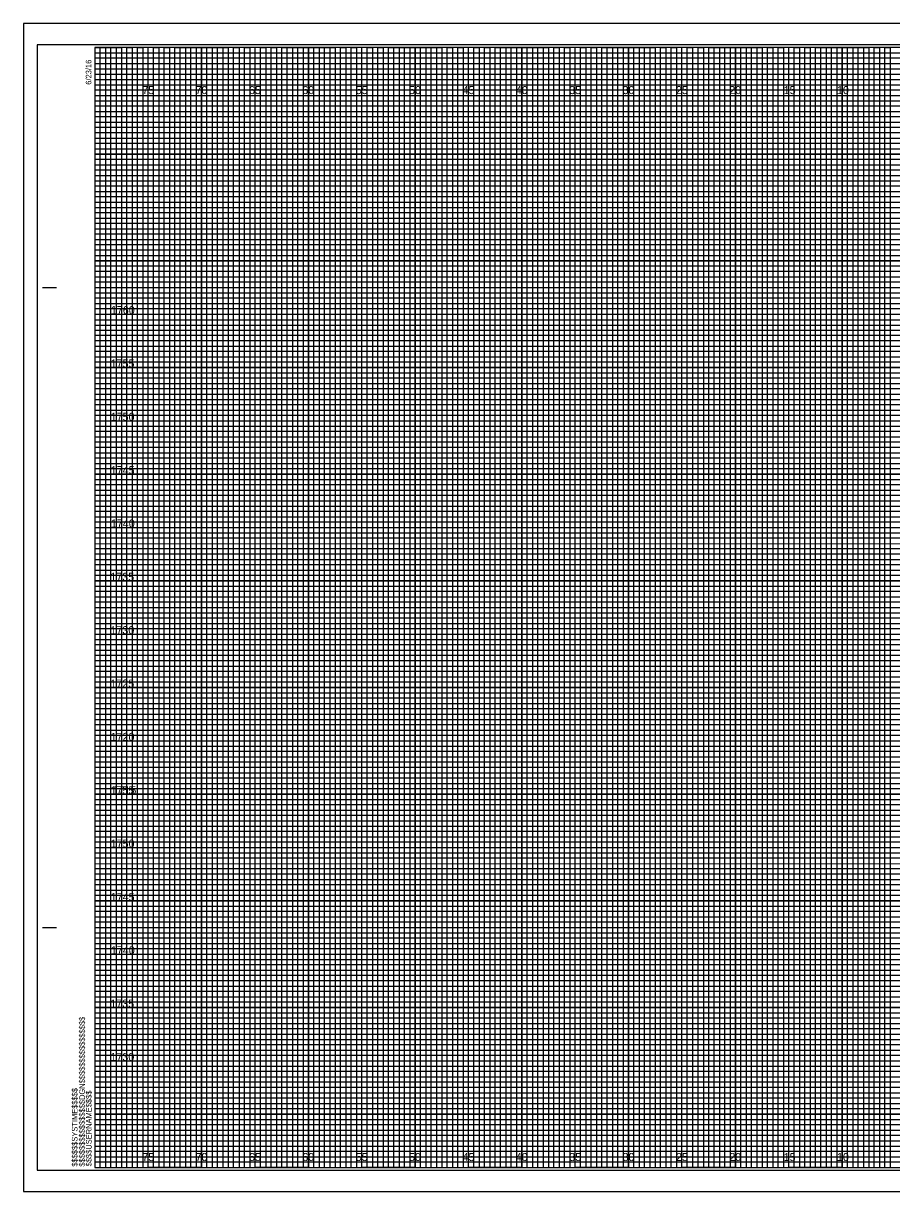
# Model space of a CAD drawing. Extents: x -7 to 162, y -2 to 437.
# Drawn here: x -6.7 to 74.6, y -2.3 to 107.3 of the extents above; entities that cross this region are included whole.
import ezdxf

# ---------------------------------------------------------------- set-up
doc = ezdxf.new("R2010")
doc.units = 0
for name, color, linetype in [('Raster_Level_0', 7, 'Continuous'), ('Scratch_Level_3', 7, 'Continuous'), ('Sheet Cross Section CELL', 7, 'Continuous'), ('Sheet Cross Section Grid Major CELL', 7, 'Continuous'), ('Sheet Cross Section Grid Middle CELL', 7, 'Continuous'), ('Sheet Cross Section Grid Minor 1 CELL', 7, 'Continuous'), ('Sheet Cross Section Grid Minor 2 CELL', 7, 'Continuous'), ('Sheet Cutting Line CELL', 7, 'Continuous'), ('Sheet DOT Grid CELL', 7, 'Continuous'), ('Sheet Plot Border Inside CELL', 7, 'Continuous'), ('Sheet Plot Border Outside CELL', 7, 'Continuous')]:
    doc.layers.add(name, color=color, linetype=linetype)

msp = doc.modelspace()

# ---------------------------------------------------------------- linework, layer by layer
at = {"layer": 'Sheet Cross Section CELL'}
for p, q in [((-4.9, 82.5), (-3.65, 82.5)), ((-4.85, 82.5), (-3.6, 82.5)), ((-4.9, 22.5), (-3.65, 22.5)), ((-4.85, 22.5), (-3.6, 22.5)), ((0, 0), (0, 0)), ((0, 0), (0, 0)), ((0, 0), (0, 0)), ((0, 0), (0, 0)), ((0, 0), (0, 0)), ((0, 0), (0, 0)), ((0, 0), (0, 0))]:
    msp.add_line(p, q, dxfattribs=at)
msp.add_lwpolyline([(160, 105), (0, 105), (0, 0), (160, 0)], close=True, dxfattribs=at)
at = {"layer": 'Sheet Cross Section Grid Major CELL'}
for p, q in [((5, 105), (0, 105)), ((5, 0), (5, 105)), ((15, 105), (10, 105)), ((10, 105), (10, 0)), ((15, 0), (15, 105)), ((25, 105), (20, 105)), ((20, 105), (20, 0)), ((25, 0), (25, 105)), ((35, 105), (30, 105)), ((30, 105), (30, 0)), ((35, 0), (35, 105)), ((45, 105), (40, 105)), ((40, 105), (40, 0)), ((45, 0), (45, 105)), ((55, 105), (50, 105)), ((50, 105), (50, 0)), ((55, 0), (55, 105)), ((65, 105), (60, 105)), ((60, 105), (60, 0)), ((65, 0), (65, 105)), ((75, 105), (70, 105)), ((70, 105), (70, 0)), ((10, 0), (5, 0)), ((20, 0), (15, 0)), ((30, 0), (25, 0)), ((40, 0), (35, 0)), ((50, 0), (45, 0)), ((60, 0), (55, 0)), ((70, 0), (65, 0))]:
    msp.add_line(p, q, dxfattribs=at)
for points in [[(0, 100), (160, 100), (160, 95), (0, 95)], [(0, 90), (160, 90), (160, 85), (0, 85)], [(0, 80), (160, 80), (160, 75), (0, 75)], [(0, 70), (160, 70), (160, 65), (0, 65)], [(0, 60), (160, 60), (160, 55), (0, 55)], [(0, 50), (160, 50), (160, 45), (0, 45)], [(0, 40), (160, 40), (160, 35), (0, 35)], [(0, 30), (160, 30), (160, 25), (0, 25)], [(0, 20), (160, 20), (160, 15), (0, 15)], [(0, 10), (160, 10), (160, 5), (0, 5)]]:
    msp.add_lwpolyline(points, dxfattribs=at)
at = {"layer": 'Sheet Cross Section Grid Middle CELL'}
for points in [[(0, 105), (2.5, 105), (2.5, 0), (7.5, 0), (7.5, 105), (12.5, 105), (12.5, 0), (17.5, 0), (17.5, 105), (22.5, 105), (22.5, 0), (27.5, 0), (27.5, 105), (32.5, 105), (32.5, 0), (37.5, 0), (37.5, 105), (42.5, 105), (42.5, 0), (47.5, 0), (47.5, 105), (52.5, 105), (52.5, 0), (57.5, 0), (57.5, 105), (62.5, 105), (62.5, 0), (67.5, 0), (67.5, 105), (72.5, 105), (72.5, 0), (77.5, 0)], [(0, 102.5), (137.5, 102.5)], [(0, 92.5), (160, 92.5), (160, 97.5), (0, 97.5)], [(0, 82.5), (160, 82.5), (160, 87.5), (0, 87.5)], [(0, 72.5), (160, 72.5), (160, 77.5), (0, 77.5)], [(0, 62.5), (160, 62.5), (160, 67.5), (0, 67.5)], [(0, 52.5), (160, 52.5), (160, 57.5), (0, 57.5)], [(0, 42.5), (160, 42.5), (160, 47.5), (0, 47.5)], [(0, 32.5), (160, 32.5), (160, 37.5), (0, 37.5)], [(0, 22.5), (160, 22.5), (160, 27.5), (0, 27.5)], [(0, 12.5), (160, 12.5), (160, 17.5), (0, 17.5)], [(0, 2.5), (160, 2.5), (160, 7.5), (0, 7.5)]]:
    msp.add_lwpolyline(points, dxfattribs=at)
at = {"layer": 'Sheet Cross Section Grid Minor 1 CELL'}
for p, q in [((0, 104.5), (130, 104.5)), ((130, 103.99), (0, 103.99)), ((0, 103.99), (0, 103.5)), ((0, 103.5), (130, 103.5)), ((130, 102.95), (0, 102.95)), ((0, 102.95), (0, 102)), ((0, 102), (160, 102))]:
    msp.add_line(p, q, dxfattribs=at)
for points in [[(0, 101.5), (135, 101.5), (160, 101.5), (160, 101), (0, 101)], [(0, 100.5), (160, 100.5), (160, 99.5), (0, 99.5)], [(0, 99), (160, 99), (160, 98.5), (0, 98.49)], [(0, 98), (160, 98), (160, 97), (0, 97)], [(0, 96.5), (160, 96.5), (160, 96), (0, 96)], [(0, 95.5), (160, 95.5), (160, 94.5), (0, 94.5)], [(0, 94), (160, 94), (160, 93.5), (0, 93.5)], [(0, 93), (160, 93), (160, 92), (0, 92)], [(0, 91.5), (160, 91.5), (160, 91), (0, 91)], [(0, 90.5), (160, 90.5), (160, 89.5), (0, 89.5)], [(0, 89), (160, 89), (160, 88.5), (0, 88.5)], [(0, 88), (160, 88), (160, 86.98), (160, 86.5), (160, 86), (0, 86)], [(0, 87), (160, 87), (160, 86.5), (0, 86.5)], [(0, 85.5), (160, 85.5), (160, 84.5), (0, 84.52)], [(0, 84.52), (160, 84.5), (160, 84), (0, 84)], [(0, 83.5), (160, 83.5), (160, 83), (0, 83)], [(0, 82), (160, 82), (160, 81.5), (0, 81.5)], [(0, 81), (160, 81), (160, 80.5), (0, 80.5)], [(-0.04, 79.45), (160, 79.45), (160, 78.94), (-0.04, 78.94)], [(0, 78.5), (160, 78.5), (160, 78), (0, 78)], [(0, 77), (160, 77), (160, 76.5), (0, 76.5)], [(0, 76), (160, 76), (160, 75.5), (0, 75.5)], [(0, 74.5), (160, 74.5), (160, 74), (0, 74)], [(0, 73.5), (160, 73.5), (160, 73), (0, 73)], [(0, 72), (160, 72), (160, 71.5), (0, 71.5)], [(0, 71), (160, 71), (160, 70.5), (0, 70.5)], [(0, 69.5), (160, 69.5), (160, 68.99), (0, 69)], [(0, 68.5), (160, 68.5), (160, 68), (0, 68)], [(0, 67), (160, 67), (160, 66.5), (0, 66.5)], [(0, 66), (160, 66), (160, 65.5), (0, 65.5)], [(0, 64.5), (160, 64.5), (160, 64), (0, 64)], [(0, 63.5), (160, 63.5), (160, 63), (0, 63)], [(0, 62), (160, 62), (160, 61.5), (0, 61.5)], [(0, 61), (160, 61), (160, 60.5), (0, 60.5)], [(0, 59.5), (160, 59.5), (160, 59), (0, 59)], [(0, 58.5), (160.03, 58.45), (160, 58), (0, 58)], [(0, 57), (160, 57), (160, 56.5), (0, 56.5)], [(0, 56), (160, 56), (160, 55.5), (0, 55.5)], [(0, 54.5), (160, 54.5), (160, 54), (0, 54)], [(0, 53.5), (160, 53.5), (160, 53), (0, 53)], [(0, 52), (160, 52), (160, 51.5), (0, 51.5)], [(0, 51), (160, 51), (160, 50.5), (0, 50.5)], [(0, 49.5), (160, 49.5), (160, 49), (0, 49)], [(0, 48.5), (160, 48.5), (160, 48), (0, 48)], [(0, 47), (160, 47), (160, 46.5), (0, 46.5)], [(0, 46), (160, 46), (160, 45.5), (0, 45.5)], [(0, 44.5), (160, 44.5), (160, 44), (0, 44)], [(0, 43.5), (160, 43.5), (160, 43), (0, 43)], [(0, 42), (160, 42), (160, 41.5), (0, 41.5)], [(0, 41), (160, 41), (160, 40.5), (0, 40.5)], [(0, 39.5), (160, 39.5), (160, 38.99), (0, 39)], [(0, 38.5), (160, 38.5), (160, 38), (0, 38)], [(0, 37), (160, 37), (160, 36.5), (0, 36.5)], [(0, 36), (160, 36), (160, 35.5), (0, 35.5)], [(0, 34.5), (160, 34.5), (160, 34), (0, 34)], [(0, 33.5), (160, 33.5), (160, 33), (0, 33)], [(0, 32), (160, 32), (160, 31.5), (0, 31.5)], [(0, 31), (160, 31), (160, 30.5), (0, 30.5)], [(0, 29.5), (160, 29.5), (160, 29), (0, 29)], [(0, 28.5), (160.03, 28.46), (160, 28), (0, 28)], [(0, 27), (160, 27), (160, 26.5), (0, 26.5)], [(0, 26), (160, 26), (160, 25.5), (0, 25.5)], [(0, 24.5), (160, 24.5), (160, 24), (0, 24)], [(0, 23.5), (160, 23.5), (160, 23), (0, 23)], [(0, 22), (160, 22), (160, 21.5), (0, 21.5)], [(0, 21), (160, 21), (160, 20.5), (0, 20.5)], [(0, 19.5), (160, 19.5), (160, 19), (0, 19)], [(0, 18.5), (160, 18.5), (160, 18), (0, 18)], [(0, 17), (160, 17), (160, 16.5), (0, 16.5)], [(0, 16), (160, 16), (160, 15.5), (0, 15.5)], [(0, 14.5), (160, 14.5), (160, 14), (0, 14)], [(0, 13.5), (160, 13.5), (160, 13), (0, 13)], [(0, 12), (160, 12), (160, 11.5), (0, 11.5)], [(0, 11), (160, 11), (160, 10.5), (0, 10.5)], [(0, 9.5), (160, 9.5), (160, 9), (0, 9)], [(0, 8.5), (160, 8.5), (160, 8), (0, 8)], [(0, 7), (160, 7), (160, 6.5), (0, 6.5)], [(0, 6), (160, 6), (160, 5.5), (0, 5.5)], [(0, 4.5), (160, 4.5), (160, 4), (0, 4)], [(0, 3.5), (160, 3.5), (160, 3), (0, 3)], [(0, 2), (160, 2), (160, 1.5), (0, 1.5)], [(0, 1), (160, 1), (160, 0.5), (0, 0.5)]]:
    msp.add_lwpolyline(points, dxfattribs=at)
at = {"layer": 'Sheet Cross Section Grid Minor 2 CELL'}
for points in [[(0, 0), (0.5, 0), (0.5, 105), (1, 105), (1, 0)], [(1, 0), (1.5, 0), (1.5, 105), (2, 105), (2, 0)], [(2.5, 0), (3, 0), (3, 105), (3.5, 105), (3.5, 0)], [(3.5, 0), (4, 0), (4, 105), (4.5, 105), (4.5, 0)], [(5, 0), (5.5, 0), (5.5, 105), (6, 105), (6, 0)], [(6, 0), (6.5, 0), (6.5, 105), (7, 105), (7, 0)], [(7.5, 0), (8, 0), (8, 105), (8.5, 105), (8.5, 0)], [(8.5, 0), (9, 0), (9, 105), (9.5, 105), (9.5, 0)], [(10, 0), (10.5, 0), (10.5, 105), (11, 105), (11, 0)], [(11, 0), (11.5, 0), (11.5, 105), (12, 105), (12, 0)], [(12.5, 0), (13, 0), (13, 105), (13.5, 105), (13.5, 0)], [(13.5, 0), (14, 0), (14, 105), (14.5, 105), (14.5, 0)], [(15, 0), (15.5, 0), (15.5, 105), (16, 105), (16, 0)], [(16, 0), (16.5, 0), (16.5, 105), (17, 105), (17, 0)], [(17.5, 0), (18, 0), (18, 105), (18.5, 105), (18.5, 0)], [(18.5, 0), (19, 0), (19, 105), (19.5, 105), (19.5, 0)], [(20, 0), (20.5, 0), (20.5, 105), (21, 105), (21, 0)], [(21, 0), (21.5, 0), (21.5, 105), (22, 105), (22, 0)], [(22.5, 0), (23, 0), (23, 105), (23.5, 105), (23.5, 0)], [(23.5, 0), (24, 0), (24, 105), (24.5, 105), (24.5, 0)], [(25, 0), (25.5, 0), (25.5, 105), (26, 105), (26, 0)], [(26, 0), (26.5, 0), (26.5, 105), (27, 105), (27, 0)], [(27.5, 0), (28, 0), (28, 105), (28.5, 105), (28.5, 0)], [(28.5, 0), (29, 0), (29, 105), (29.5, 105), (29.5, 0)], [(30, 0), (30.5, 0), (30.5, 105), (31, 105), (31, 0)], [(31, 0), (31.5, 0), (31.5, 105), (32, 105), (32, 0)], [(32.5, 0), (33, 0), (33, 105), (33.5, 105), (33.5, 0)], [(33.5, 0), (34, 0), (34, 105), (34.5, 105), (34.5, 0)], [(35, 0), (35.5, 0), (35.5, 105), (36, 105), (36, 0)], [(36, 0), (36.5, 0), (36.5, 105), (37, 105), (37, 0)], [(37.5, 0), (38, 0), (38, 105), (38.5, 105), (38.5, 0)], [(38.5, 0), (39, 0), (39, 105), (39.5, 105), (39.5, 0)], [(40, 0), (40.5, 0), (40.5, 105), (41, 105), (41, 0)], [(41, 0), (41.5, 0), (41.5, 105), (42, 105), (42, 0)], [(42.5, 0), (43, 0), (43, 105), (43.5, 105), (43.5, 0)], [(43.5, 0), (44, 0), (44, 105), (44.5, 105), (44.5, 0)], [(45, 0), (45.5, 0), (45.5, 105), (46, 105), (46, 0)], [(46, 0), (46.5, 0), (46.5, 105), (47, 105), (47, 0)], [(47.5, 0), (48, 0), (48, 105), (48.5, 105), (48.5, 0)], [(48.5, 0), (49, 0), (49, 105), (49.5, 105), (49.5, 0)], [(50, 0), (50.5, 0), (50.5, 105), (51, 105), (51, 0)], [(51, 0), (51.5, 0), (51.5, 105), (52, 105), (52, 0)], [(52.5, 0), (53, 0), (53, 105), (53.5, 105), (53.5, 0)], [(53.5, 0), (54, 0), (54, 105), (54.5, 105), (54.5, 0)], [(55, 0), (55.5, 0), (55.5, 105), (56, 105), (56, 0)], [(56, 0), (56.5, 0), (56.5, 105), (57, 105), (57, 0)], [(57.5, 0), (58, 0), (58, 105), (58.5, 105), (58.5, 0)], [(58.5, 0), (59, 0), (59, 105), (59.5, 105), (59.5, 0)], [(60, 0), (60.5, 0), (60.5, 105), (61, 105), (61, 0)], [(61, 0), (61.5, 0), (61.5, 105), (62, 105), (62, 0)], [(62.5, 0), (63, 0), (63, 105), (63.5, 105), (63.5, 0)], [(63.5, 0), (64, 0), (64, 105), (64.5, 105), (64.5, 0)], [(65, 0), (65.5, 0), (65.5, 105), (66, 105), (66, 0)], [(66, 0), (66.5, 0), (66.5, 105), (67, 105), (67, 0)], [(67.5, 0), (68, 0), (68, 105), (68.5, 105), (68.5, 0)], [(68.5, 0), (69, 0), (69, 105), (69.5, 105), (69.5, 0)], [(70, 0), (70.5, 0), (70.5, 105), (71, 105), (71, 0)], [(71, 0), (71.5, 0), (71.5, 105), (72, 105), (72, 0)], [(72.5, 0), (73, 0), (73, 105), (73.5, 105), (73.5, 0)], [(73.5, 0), (74, 0), (74, 105), (74.5, 105), (74.5, 0)]]:
    msp.add_lwpolyline(points, dxfattribs=at)
at = {"layer": 'Sheet Cutting Line CELL'}
for p, q in [((161.65, 107.25), (-6.7, 107.25)), ((-6.7, 107.25), (-6.7, -2.25)), ((-6.7, -2.25), (161.65, -2.25))]:
    msp.add_line(p, q, dxfattribs=at)
at = {"layer": 'Sheet DOT Grid CELL'}
for p, q in [((5, 0), (5, 105)), ((10, 0), (10, 105)), ((15, 0), (15, 105)), ((20, 0), (20, 105)), ((25, 0), (25, 105)), ((30, 0), (30, 105)), ((35, 0), (35, 105)), ((40, 0), (40, 105)), ((45, 0), (45, 105)), ((50, 0), (50, 105)), ((55, 0), (55, 105)), ((60, 0), (60, 105)), ((65, 0), (65, 105)), ((70, 0), (70, 105)), ((0, 100), (160, 100)), ((0, 95), (160, 95)), ((0, 90), (160, 90)), ((0, 85), (160, 85)), ((0, 80), (160, 80)), ((0, 75), (160, 75)), ((0, 70), (160, 70)), ((0, 65), (160, 65)), ((0, 60), (160, 60)), ((0, 55), (160, 55)), ((0, 50), (160, 50)), ((0, 45), (160, 45)), ((0, 40), (160, 40)), ((0, 35), (160, 35)), ((0, 30), (160, 30)), ((0, 25), (160, 25)), ((0, 20), (160, 20)), ((0, 15), (160, 15)), ((0, 10), (160, 10)), ((0, 5), (160, 5))]:
    msp.add_line(p, q, dxfattribs=at)
at = {"layer": 'Sheet Plot Border Inside CELL'}
msp.add_lwpolyline([(-5.4, -0.25), (161.2, -0.25), (161.2, 105.25), (-5.4, 105.25)], close=True, dxfattribs=at)
at = {"layer": 'Sheet Plot Border Outside CELL'}
msp.add_lwpolyline([(-6.7, -2.25), (161.65, -2.25), (161.65, 107.25), (-6.7, 107.25)], close=True, dxfattribs=at)

# ---------------------------------------------------------------- texts
at = {"layer": 'Raster_Level_0'}
for s, p in [('75', (4.44, 100.62)), ('70', (9.43, 100.62)), ('65', (14.44, 100.62)), ('60', (19.43, 100.62)), ('55', (24.44, 100.62)), ('50', (29.43, 100.62)), ('45', (34.44, 100.62)), ('40', (39.43, 100.62)), ('35', (44.44, 100.62)), ('30', (49.43, 100.62)), ('25', (54.44, 100.62)), ('20', (59.43, 100.62)), ('15', (64.53, 100.62)), ('10', (69.52, 100.62)), ('75', (4.44, 0.62)), ('70', (9.43, 0.62)), ('65', (14.44, 0.62)), ('60', (19.43, 0.62)), ('55', (24.44, 0.62)), ('50', (29.43, 0.62)), ('45', (34.44, 0.62)), ('40', (39.43, 0.62)), ('35', (44.44, 0.62)), ('30', (49.43, 0.62)), ('25', (54.44, 0.62)), ('20', (59.43, 0.62)), ('15', (64.53, 0.62)), ('10', (69.52, 0.62))]:
    msp.add_text(s, height=0.75, dxfattribs=at).set_placement(p)
at = {"layer": 'Scratch_Level_3'}
for s, p in [('1760', (1.5, 80)), ('1755', (1.47, 75)), ('1750', (1.48, 70)), ('1745', (1.49, 65)), ('1740', (1.5, 60)), ('1735', (1.45, 55)), ('1730', (1.46, 50)), ('1725', (1.46, 45)), ('1720', (1.47, 40)), ('1755', (1.47, 35)), ('1715', (1.65, 35)), ('1750', (1.48, 30)), ('1745', (1.49, 25)), ('1740', (1.5, 20)), ('1735', (1.45, 15)), ('1730', (1.46, 10))]:
    msp.add_text(s, height=0.75, dxfattribs=at).set_placement(p)
at = {"layer": 'Sheet Cross Section CELL'}
for s, p in [('6/23/16', (-0.33, 101.5)), ('$$$$$$$$$$$$$$$$DGN$$$$$$$$$$$$$$$$', (-0.94, 0.09)), ('$$$$$$SYSTIME$$$$$', (-1.63, 0.09)), ('$$$$USERNAME$$$$', (-0.31, 0.12))]:
    msp.add_text(s, height=0.525, rotation=90, dxfattribs=at).set_placement(p)

doc.saveas('drawing.dxf')
